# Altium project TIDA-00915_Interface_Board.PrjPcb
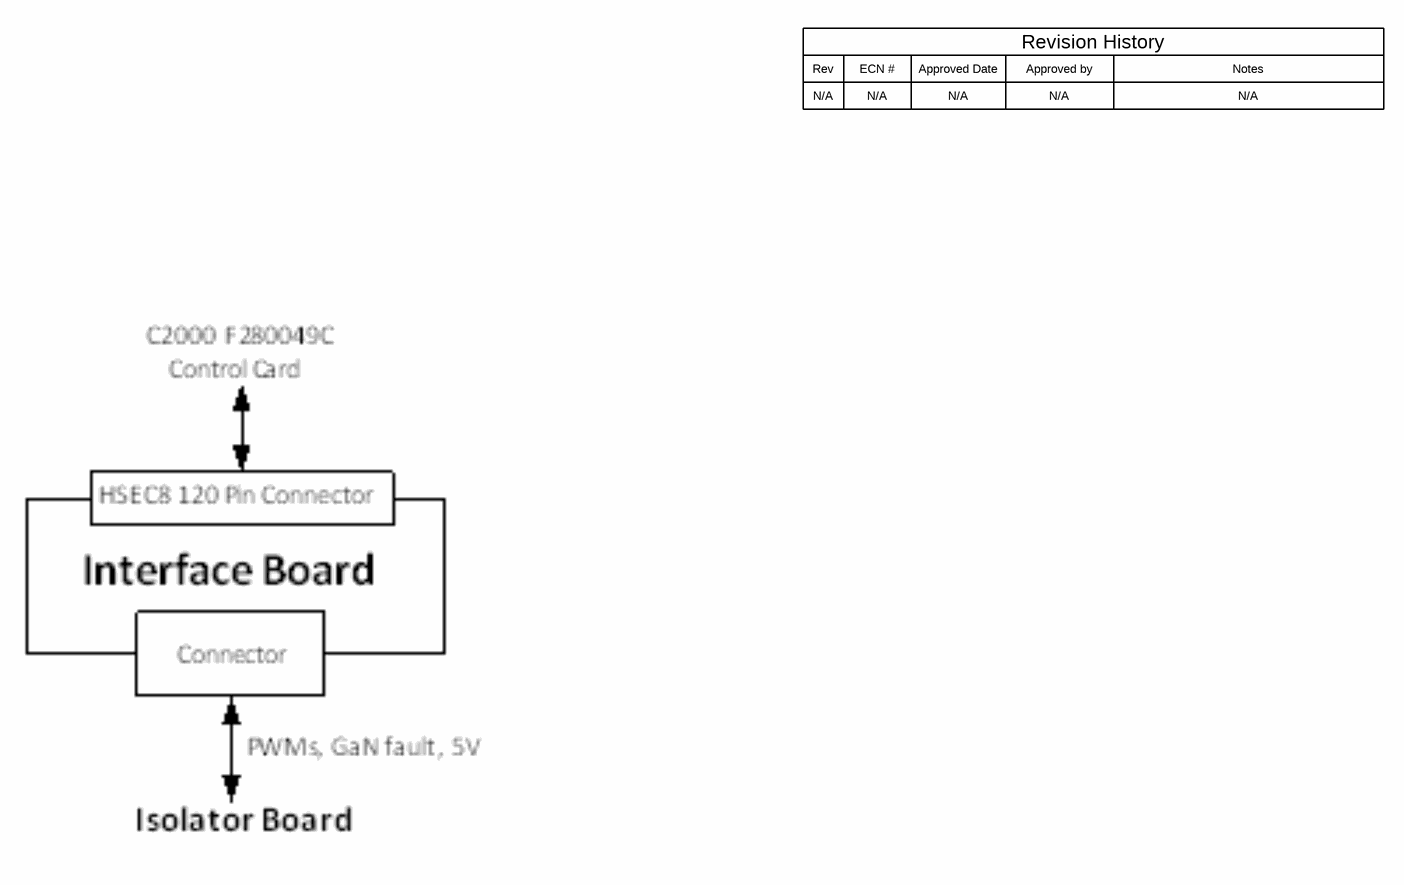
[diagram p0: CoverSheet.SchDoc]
TID: 00915; TechSupport: http://www.ti.com/support; SCH_Rev: E1; PRJ_Title: TIDA-00915_Interface_Board; PRJ_Number: TIDA-00915_Interface_Board; PRJ_Customer: Public Release; PCB_Rev: E1; CopyrightYear: 2019
3 sheets, 16 parts. Net scope: global (net labels, ports and power ports of the same name join across sheets).
Board file: TIDA-00915_Interface_Board.PcbDoc
Sheets:
  CoverSheet.SchDoc
  EVM_Hardware.SchDoc
  Connector.SchDoc

## Sheet CoverSheet.SchDoc
size 431 x 279 mm; Date: Not shown in title block; ApprovedBy: Not shown in title block; CheckedBy: Not shown in title block; Author: Not shown in title block; CompanyName: Not shown in title block; Engineer: Not shown in title block; Organization: Not shown in title block; Address1: Not shown in title block; Address2: Not shown in title block; Address3: Not shown in title block; Address4: Not shown in title block; DocumentNumber: 1; Revision: Use project parameter SCH_Rev; SheetNumber: 1; SheetTotal: 3; PageSetup: Record=PageOptions¦CenterHorizontal=True¦CenterVertical=True¦PrintScale=1.00¦XCorrection=1.00¦YCorrection=1.00¦PrintKind=0¦BorderSize=5000000¦LeftOffset=0¦BottomOffset=0¦Orientation=2¦PaperLength=1000¦PaperWidth=1000¦Scale=100¦PaperSource=15¦PrintQuality=600¦MediaType=1¦DitherType=10¦PaperKind=Letter¦PrintScaleMode=1

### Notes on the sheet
- Rev
- N/A
- ECN #
- Approved Date
- Approved by
- Revision History
- Notes

## Sheet EVM_Hardware.SchDoc
size 431 x 279 mm; Date: Not shown in title block; ApprovedBy: Not shown in title block; CheckedBy: Not shown in title block; Author: Not shown in title block; CompanyName: Not shown in title block; Engineer: Not shown in title block; Organization: Not shown in title block; Address1: Not shown in title block; Address2: Not shown in title block; Address3: Not shown in title block; Address4: Not shown in title block; DocumentNumber: 1; Revision: Use project parameter SCH_Rev; SheetNumber: 3; SheetTotal: 3; PageSetup: Record=PageOptions¦CenterHorizontal=True¦CenterVertical=True¦PrintScale=1.00¦XCorrection=1.00¦YCorrection=1.00¦PrintKind=0¦BorderSize=5000000¦LeftOffset=0¦BottomOffset=0¦Orientation=2¦PaperLength=1000¦PaperWidth=1000¦Scale=100¦PaperSource=15¦PrintQuality=600¦MediaType=1¦DitherType=10¦PaperKind=Letter¦PrintScaleMode=1
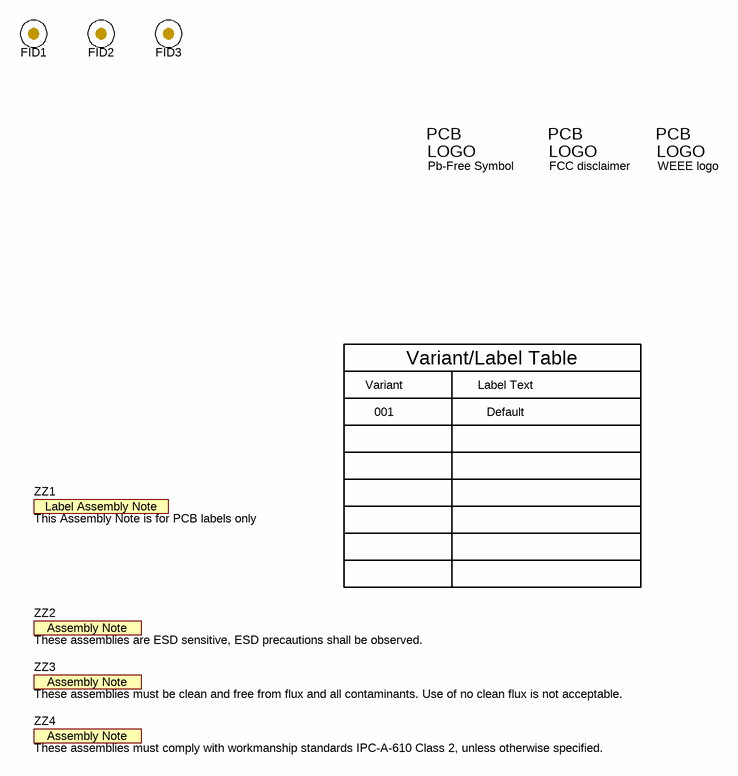
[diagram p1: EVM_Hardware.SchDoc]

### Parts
FID1  Fiducial  [Fiducial10-20]  (value not drawn)
FID2  Fiducial  [Fiducial10-20]  (value not drawn)
FID3  Fiducial  [Fiducial10-20]  (value not drawn)
Logo2  Pb-Free Symbol  [Pb-Free_Overlay_Small]  (no BOM)
Logo3  FCC disclaimer  [FCC_disclaimer]  (no BOM)
Logo4  WEEE logo  [WEEE_Minimum]  (no BOM)
ZZ1  This Assembly Note is for PCB labels only  [AssemblyNoteLabel]  (no BOM)
ZZ2  These assemblies are ESD sensitive, ESD precautions shall be observed.  [AssemblyNote]  (no BOM)
ZZ3  These assemblies must be clean and free from flux and all contaminants. Use of no clean flux is not acceptable.  [AssemblyNote]  (no BOM)
ZZ4  These assemblies must comply with workmanship standards IPC-A-610 Class 2, unless otherwise specified.  [AssemblyNote]  (no BOM)

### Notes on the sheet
- Variant
- Variant/Label Table
- Label Text
- 001
- Default

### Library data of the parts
FID1-FID3 = CMP-0077181-1: Fiducial mark.  There is nothing to buy or mount.
Logo2 = CMP-0074839-1: SymbolCreator: a0412235; Library Reference: Logo
Logo3 = CMP-0074847-1: FCC_disclaimer; Library Reference: Logo
Logo4 = CMP-0074769-1
ZZ1 = CMP-0003616-3
ZZ2 = CMP-0077236-1
ZZ3 = CMP-0077237-1
ZZ4 = CMP-0077238-1

## Sheet Connector.SchDoc
size 431 x 279 mm; Date: Not shown in title block; ApprovedBy: Not shown in title block; CheckedBy: Not shown in title block; Author: Not shown in title block; CompanyName: Not shown in title block; Engineer: Not shown in title block; Organization: Not shown in title block; Address1: Not shown in title block; Address2: Not shown in title block; Address3: Not shown in title block; Address4: Not shown in title block; DocumentNumber: 1; Revision: Use project parameter SCH_Rev; SheetNumber: 2; SheetTotal: 3; PageSetup: Record=PageOptions¦CenterHorizontal=True¦CenterVertical=True¦PrintScale=1.00¦XCorrection=1.00¦YCorrection=1.00¦PrintKind=0¦BorderSize=5000000¦LeftOffset=0¦BottomOffset=0¦Orientation=2¦PaperLength=1000¦PaperWidth=1000¦Scale=100¦PaperSource=15¦PrintQuality=600¦MediaType=1¦DitherType=10¦PaperKind=Letter¦PrintScaleMode=1
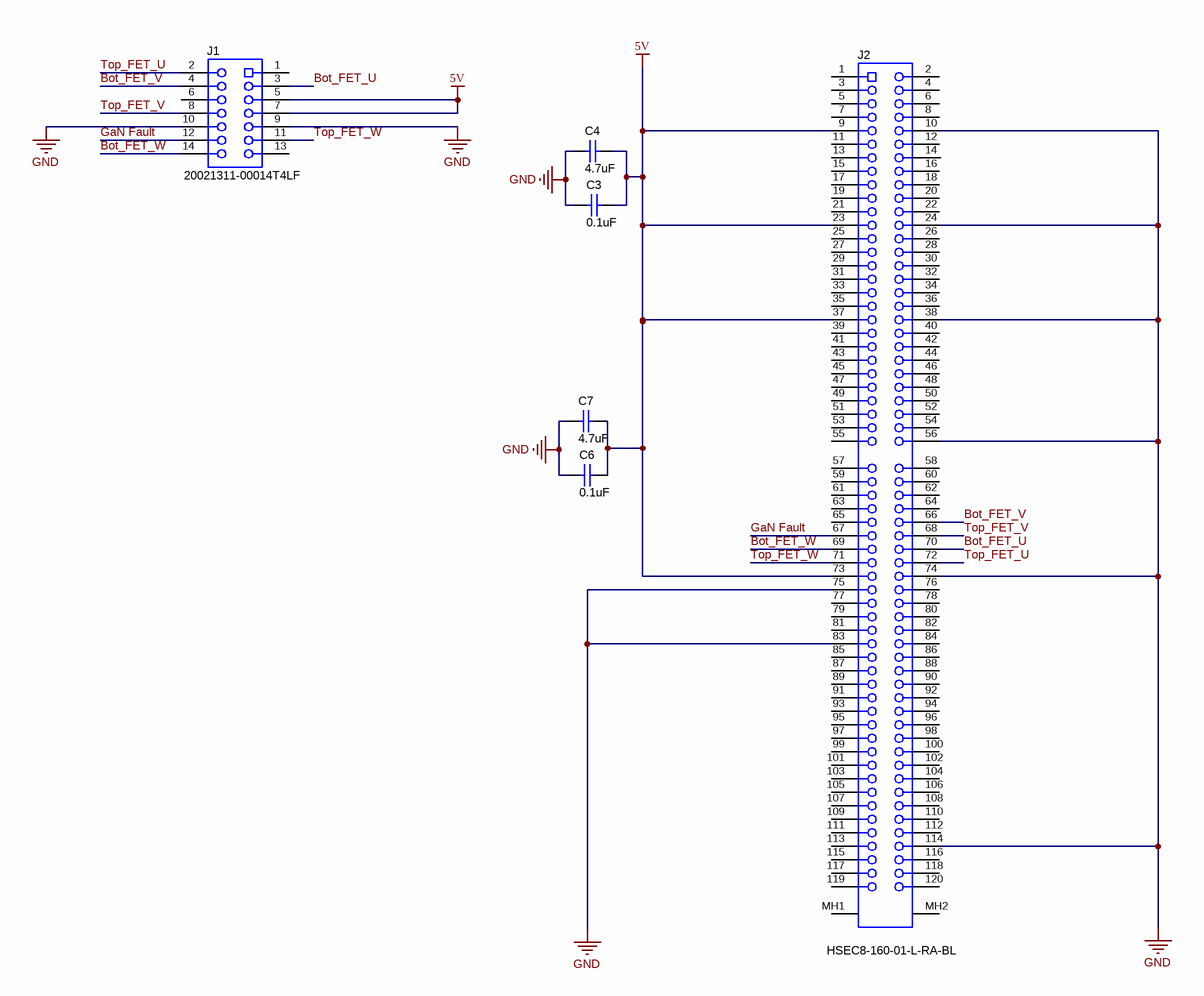
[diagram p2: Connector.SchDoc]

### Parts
C3  ValueDisplayed: 0.1uF  [0603]  (hidden comment: 06035C104KAT2A)
C4  ValueDisplayed: 4.7uF  [0805_HV]  (hidden comment: C2012X7R1V475K125AC)
C6  ValueDisplayed: 0.1uF  [0603]  (hidden comment: 06035C104KAT2A)
C7  ValueDisplayed: 4.7uF  [0805_HV]  (hidden comment: C2012X7R1V475K125AC)
J1  20021311-00014T4LF  [FCI_20021311-00014XXLF]
J2  HSEC8-160-01-L-RA-BL  [Samtec_HSEC8-160-01-x-RA-BL]

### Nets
5V: C3.1 C4.2 C6.1 C7.2 J1.5 J1.7 J2.9 J2.23 J2.37 J2.73
GND: C3.2 C4.1 C6.2 C7.1 J1.9 J1.10 J2.10 J2.24 J2.38 J2.56 J2.74 J2.75 J2.83 J2.114
Bot_FET_U: J1.3 J2.70
Bot_FET_V: J1.4 J2.66
Bot_FET_W: J1.14 J2.69
GaN Fault: J1.12 J2.67
Top_FET_U: J1.2 J2.72
Top_FET_V: J1.8 J2.68
Top_FET_W: J1.11 J2.71

Not connected (* = marked no-connect by the designer): J1 1 6 13; J2 1 2 3 4 5 6 7 8 11 12 13 14 15 16 17 18 19 20 21 22 25 26 27 28 29 30 31 32 33 34 35 36 39 40 41 42 43 44 45 46 47 48 49 50 51 52 53 54 55 57 58 59 60 61 62 63 64 65 76 77 78 79 80 81 82 84 85 86 87 88 89 90 91 92 93 94 95 96 97 98 99 100 101 102 103 104 105 106 107 108 109 110 111 112 113 115 116 117 118 119 120 MH1 MH2

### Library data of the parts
C3 C6 = CMP-0006802-4: CAP, CERM, 0.1 uF, 50 V, +/- 10%, X7R, 0603; Manufacturer: AVX; TaMin_C: -55°C; Polarized: N; SizeAreaWB_mm2: 4.68; Value1: Unknown; U/M: EA; Value: 0.1uF; TaMax_C: 125°C; SizeZ_mm: 1; SizeX_mm: 1.6; SizeY_mm: 0.8; Value2: 50V; SizeArea_mm2: 1.28; CompType: Capacitor; Cap_F: 100nF; AEC Category: Q200
C4 C7 = CMP-0007885-2: CAP, CERM, 4.7 uF, 35 V, +/- 10%, X7R, 0805; Manufacturer: TDK; TaMin_C: -55°C; ESR_ohm: 2.346m; Polarized: N; SizeAreaWB_mm2: 6.75; Value1: 0.002346 ohm; U/M: EA; Value: 4.7uF; TaMax_C: 125°C; SizeZ_mm: 1.45; SizeX_mm: 2; SizeY_mm: 1.25; Cap_Case: 0805; Value2: 35V; SizeArea_mm2: 2.5; CompType: Capacitor; Cap_F: 4.7µF; IRMS_A: 4.26021A; AEC Category: Q200
J1 = CMP-0086231-1: Receptacle, 1.27mm, 7x2, Gold, TH; Manufacturer: FCI; Voltage_V: 125V; Pitch_mm: 1.27; Gender: Female; Current_A: 1A; Row_Count: 2
J2 = CMP-0085713-1: Receptacle, 0.8mm, 60x2, Gold with Tin tail, SMT; Manufacturer: Samtec; Gender: Female; Pitch_mm: 0.8; Row_Count: 2

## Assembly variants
001: not fitted FID1 FID2 FID3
